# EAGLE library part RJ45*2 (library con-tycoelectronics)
RJ45 Low Profile Shield Type 2 For all RJ45 L, LC, LCT and X Series Models Source: www.tycoelectronics.com .. ENG_DS_1654001_1099_RJ_L_0507.pdf
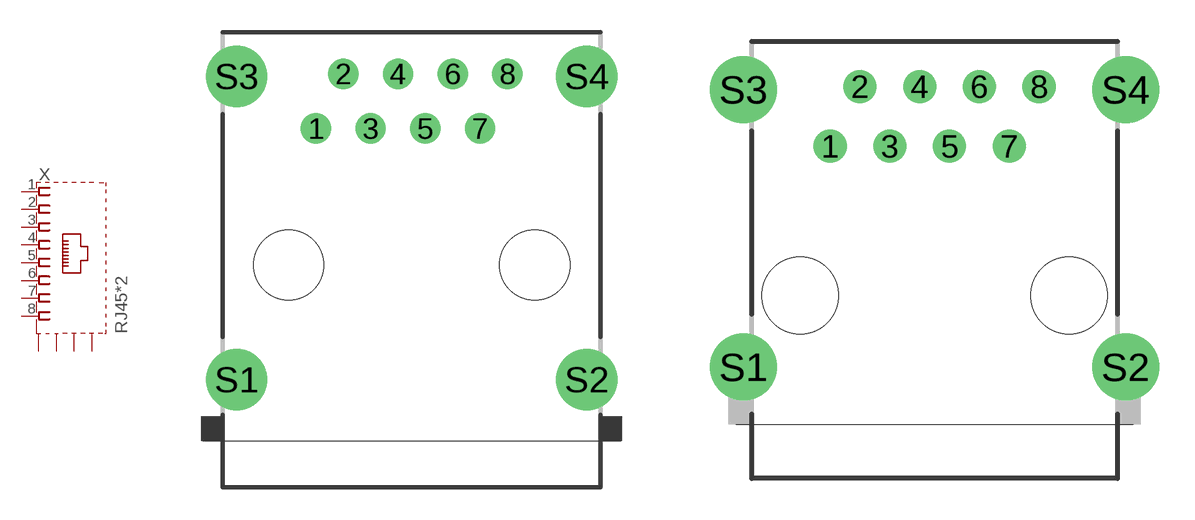
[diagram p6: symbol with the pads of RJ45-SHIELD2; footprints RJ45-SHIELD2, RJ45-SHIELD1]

Designator prefix X

## RJ45-6L2-S (MPN: RJ45-6L2-S; OC_FARNELL: unknown; OC_NEWARK: 16R6097), RJ45-6LC2-S (MPN: RJ45-6LC2-S; OC_FARNELL: unknown; OC_NEWARK: 16R6095), RJ45-6LCT2-S (OC_FARNELL: unknown; OC_NEWARK: unknown), RJ45-8L2-S (MF: TYCO ELECTRONICS; MPN: RJ45-8L2-S; OC_FARNELL: unknown; OC_NEWARK: 52K4446), RJ45-8LC2-S (MPN: RJ45-8LC2-S; OC_FARNELL: unknown; OC_NEWARK: 16R6099), RJ45-8LCT2-S (MF: TYCO ELECTRONICS; MPN: RJ45-8LCT2-S; OC_FARNELL: unknown; OC_NEWARK: 84K0524)  [RJ45-SHIELD2]
1  1  pas
2  2  pas
3  3  pas
4  4  pas
5  5  pas
6  6  pas
7  7  pas
8  8  pas
S1  S  pas
S2  S  pas
S3  S  pas
S4  S  pas

## RJ45-6L2-B (MPN: RJ45-6L2-B; OC_FARNELL: unknown; OC_NEWARK: 16R6096), RJ45-6LC2-B (MPN: RJ45-6LC2-B; OC_FARNELL: unknown; OC_NEWARK: 16R6094), RJ45-8L2-B (MF: TYCO ELECTRONICS; MPN: RJ45-8L2-B; OC_FARNELL: unknown; OC_NEWARK: 52K3810), RJ45-8LC2-B (MF: TYCO ELECTRONICS; MPN: RJ45-8LC2-B.; OC_FARNELL: unknown; OC_NEWARK: 50F1338), RJ45-8LCT2-B (MF: TYCO ELECTRONICS; MPN: RJ45-8LCT2-B; OC_FARNELL: unknown; OC_NEWARK: 91F7263)  [RJ45-SHIELD2]
Pads as for RJ45-SHIELD2

## RJ45-6L21-S (OC_FARNELL: unknown; OC_NEWARK: unknown), RJ45-6LC21-S (OC_FARNELL: unknown; OC_NEWARK: unknown), RJ45-8L21-S (OC_FARNELL: unknown; OC_NEWARK: unknown), RJ45-8LC21-S (OC_FARNELL: unknown; OC_NEWARK: unknown), RJ45-8LCT21-S (OC_FARNELL: unknown; OC_NEWARK: unknown)  [RJ45-SHIELD1]
Pads as for RJ45-SHIELD2

## RJ45-6L21-B (OC_FARNELL: unknown; OC_NEWARK: unknown), RJ45-6LC21-B (OC_FARNELL: unknown; OC_NEWARK: unknown), RJ45-8L21-B (OC_FARNELL: unknown; OC_NEWARK: unknown), RJ45-8LC21-B (OC_FARNELL: unknown; OC_NEWARK: unknown), RJ45-8LCT21-B (OC_FARNELL: unknown; OC_NEWARK: unknown)  [RJ45-SHIELD1]
Pads as for RJ45-SHIELD2

## Footprint RJ45-SHIELD2 (pad centres in mm)
RJ45 Low Profile Shield Type 2 For all RJ45 L, LC, LCT and X Series Models Source: www.tycoelectronics.com .. ENG_DS_1654001_1099_RJ_L_0507.pdf
drill 0.9 pad 1.4 round: 1 -4.445,6.35; 2 -3.175,8.89; 3 -1.905,6.35; 4 -0.635,8.89; 5 0.635,6.35; 6 1.905,8.89; 7 3.175,6.35; 8 4.445,8.89
drill 1.9 pad 2.5 round: S1 -8.128,-5.33; S2 8.128,-5.33; S3 -8.128,8.76; S4 8.128,8.76
hole 3.251 at -5.715,0
hole 3.251 at 5.715,0

## Footprint RJ45-SHIELD1 (pad centres in mm)
RJ45 Low Profile Shield Type 1 For all RJ45 N and Z Series Models Source: www.tycoelectronics.com .. ENG_DS_1654001_1099_RJ_L_0507.pdf
drill 0.9 pad 1.4 round: 1 -4.445,6.35; 2 -3.175,8.89; 3 -1.905,6.35; 4 -0.635,8.89; 5 0.635,6.35; 6 1.905,8.89; 7 3.175,6.35; 8 4.445,8.89
drill 1.9 pad 2.5 round: S1 -8.128,-3.048; S2 8.128,-3.048; S3 -8.128,8.76; S4 8.128,8.76
hole 3.251 at -5.715,0
hole 3.251 at 5.715,0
